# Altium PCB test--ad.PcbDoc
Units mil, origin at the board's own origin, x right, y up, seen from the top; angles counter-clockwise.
Board outline 2362.33 x 1685.17 mil, 2 copper layers (TopLayer, BottomLayer); 26 components, 98 nets, 129 pads, 106 vias.
Unrouted connection lines stored in the file: 5.
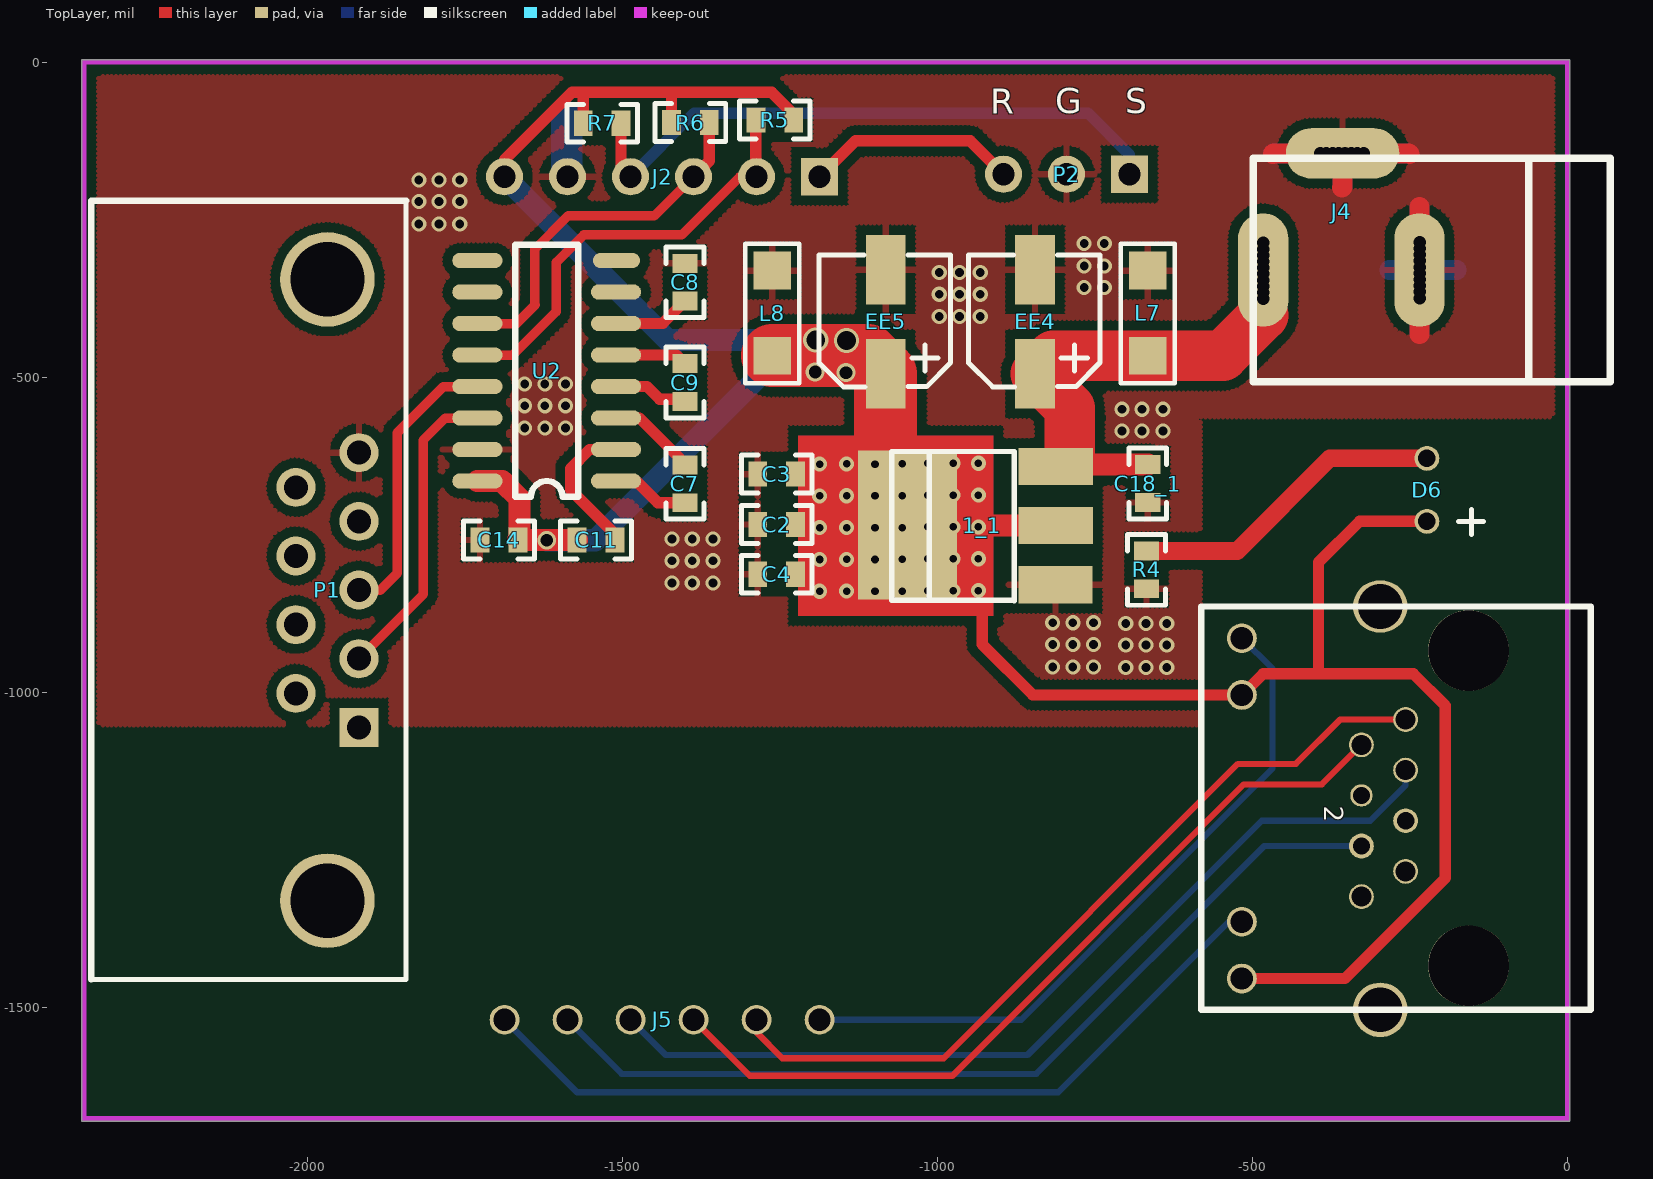
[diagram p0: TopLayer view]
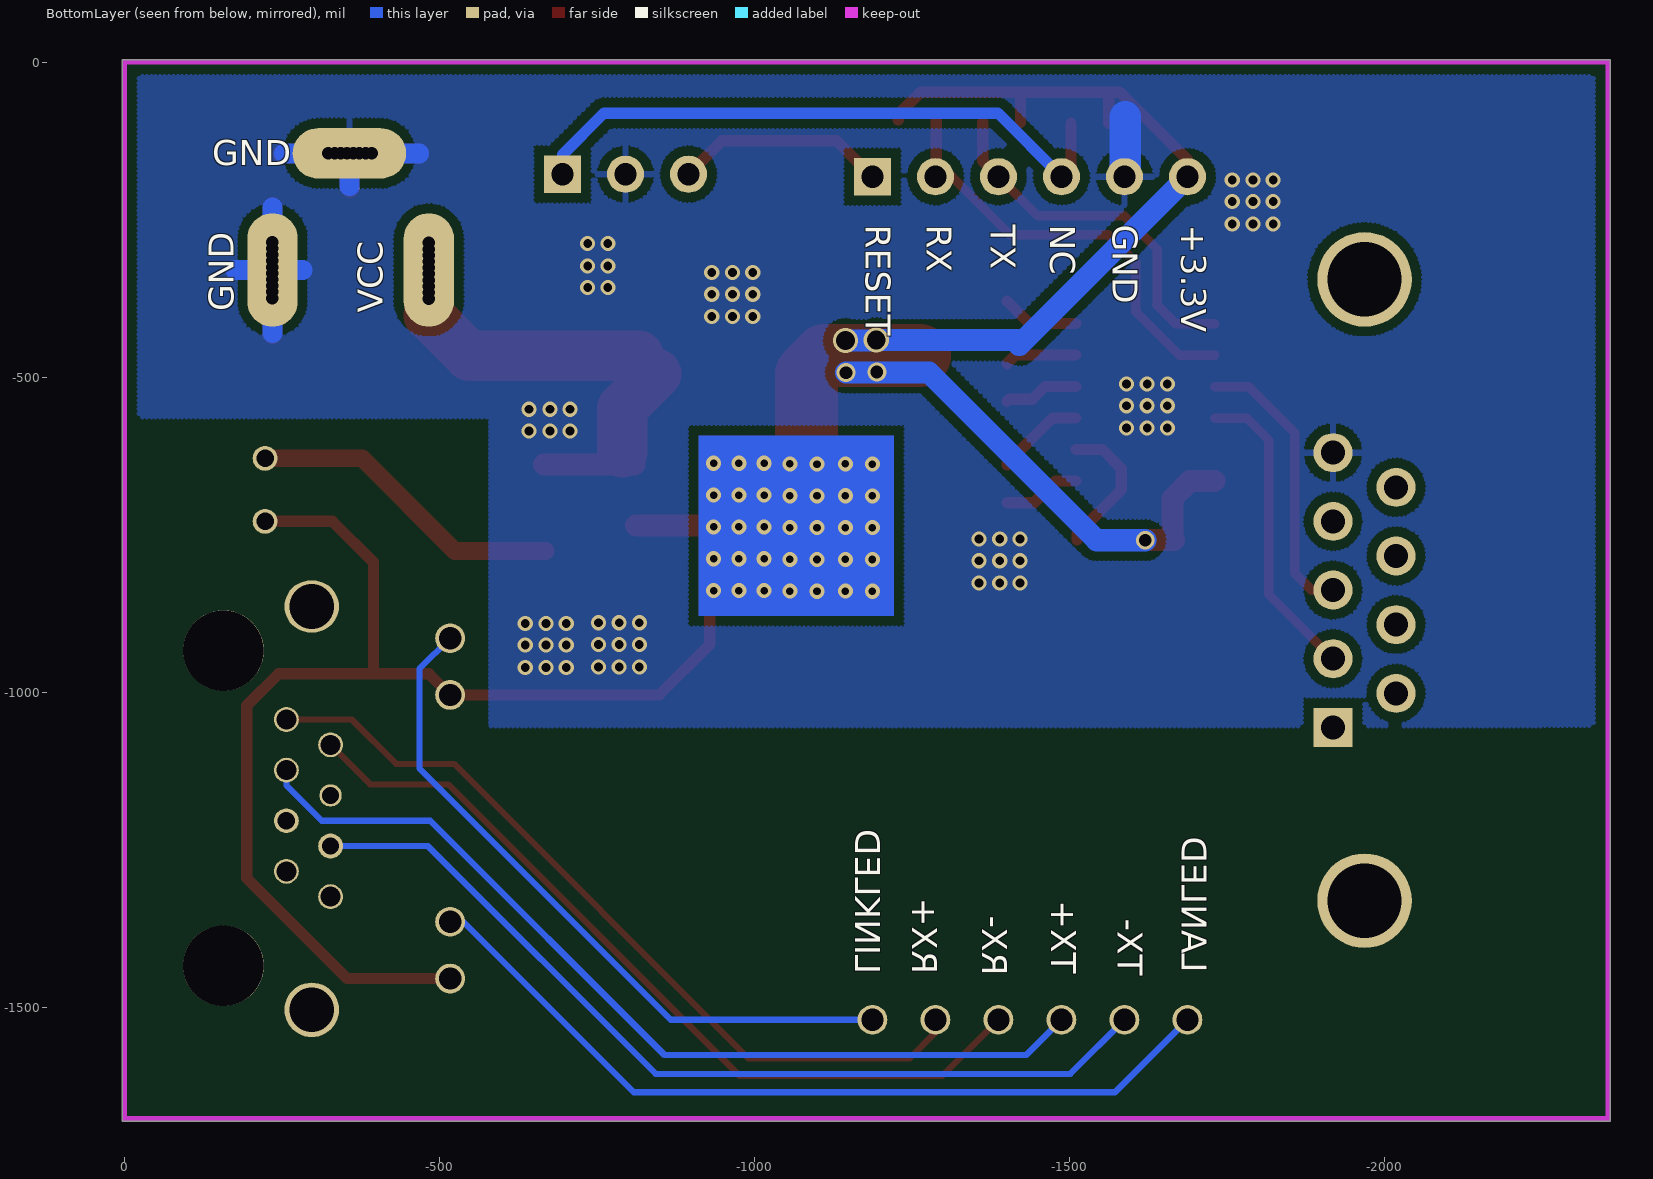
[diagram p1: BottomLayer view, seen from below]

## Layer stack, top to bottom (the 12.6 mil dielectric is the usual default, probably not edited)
TopLayer: signal copper 1.4
Dielectric: dielectric 12.6, FR-4, Dk 4.8
BottomLayer: signal copper 1.4

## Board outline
-2358.33,-1681.17 4,-1681.17 4,4 -2358.33,4

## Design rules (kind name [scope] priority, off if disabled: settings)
Clearance [All] p1: gap=15
FabricationTestPointUsage TestPointUsage [All] p1: valid=0 allowmultiple=FALSE
FabricationTestpoint Testpoint [All] p1: side=3 testpointundercomponent=TRUE minsize=40 maxsize=100 preferedsize=60 minholesize=20 maxholesize=40 preferedholesize=32 testpointgrid=1 allowsidetop=TRUE allowsidebottom=TRUE usegrid=TRUE gridtolerance=0.01
PolygonConnect [All] p1: connectstyle=Relief reliefconductorwidth=10 reliefentries=4 polygonreliefangle="90 Angle" airgapwidth=10
RoutingVias [All] p1: holewidth=28 width=50 viastyle="Through Hole" minholewidth=28 minwidth=50 maxholewidth=28 maxwidth=50
SilkscreenOverComponentPads [All] p1: minsilkscreentomaskgap=10
SolderMaskExpansion [All] p1: expansion=4
Width [All] p1: maxlimit=100 minlimit=6 preferedwidth=8
25 further rules are at their usual default settings.

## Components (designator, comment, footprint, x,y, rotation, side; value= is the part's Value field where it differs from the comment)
1_1 "LM1117-3.3V" 3-ASM-1117 -813,-828 r90 top
2 "Comment" PCBComponent_1 37,-864 r270 top
C2 "104" 2-R0603 -1285,-734 r0 top
C3 "104" 2-R0603 -1285,-654 r0 top
C4 "104" 2-R0603 -1285,-813 r0 top
C7 "0.1uf" 2-R0603 -1400.73,-699.43 r90 top
C8 "0.1uf" 2-R0603 -1400.45,-319.43 r270 top
C9 "0.1uf" 2-R0603 -1400.45,-478.62 r270 top
C11 "0.1uf" 2-R0603 -1571.73,-758.43 r0 top
C14 "0.1uf" 2-R0603 -1725.86,-758.43 r0 top
C18_1 "104" 2-R0603 -666,-699 r90 top
D6 "LED" ? -223,-729 r90 top
EE4 "100/10V" EC_D5.0_SMD -845,-495 r270 top
EE5 "100/10V" EC_D5.0_SMD -1082,-495 r270 top
J2 "Comment" HDR1X6#1 -1187,-182 r180 top
J4 "CON3" 3-POWER 73.32,-330.01 r90 top
J5 "Comment" HDR1X6#2 -1687,-1520 r0 top
L7 "9V稳压" 1206A -666,-466 r90 top
L8 "3.6V稳压" 1206A -1262,-466 r90 top
P1 "CONNECTOR DB9" "11-DB9RA/F ĸͷ" -1918,-1056 r90 top
P2 "Header 4H" HDR1X4H -695,-178 r180 top
R4 "1K" 2-R0603 -668,-836 r90 top
R5 "10K" 2-R0603 -1228,-92 r180 top
R6 "10K" 2-R0603 -1422,-96 r0 top
R7 "10K" 2-R0603 -1562,-97 r0 top
U2 "MAX3232CSE" 16-SO-16 -1510,-665 r90 top

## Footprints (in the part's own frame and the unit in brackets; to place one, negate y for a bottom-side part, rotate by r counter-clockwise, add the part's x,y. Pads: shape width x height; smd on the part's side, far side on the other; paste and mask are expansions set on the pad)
2-R0603 [mil]
  rect 30x40 smd: 1(0,0) 2(60,0)
  silkscreen extent -26,-30 86,30
3-ASM-1117 [mm]
  rect 1.5x3 smd: 1(-0.039,-0.013) 2(2.351,-0.023) 3(4.731,-0.023)
  rect 6x4 smd: 2(2.371,5.957)
  silkscreen extent -0.69,1.65 5.33,6.58
3-POWER [mil]
  oval 180x80 all layers, no hole: 1(0,556.18) 2(0,308.15)
  oval 80x180 all layers, no hole: 3(185.04,430.2)
  silkscreen extent -177,5 177,572
"11-DB9RA/F ĸͷ" [mil]
  rect 62x62 hole 38: 1(0,0)
  round 62 hole 38: 2(109,0) 3(218,0) 4(327,0) 5(436,0) 6(54,100) 7(163,100) 8(272,100) 9(381,100)
  round 150 hole 118.11: 10(-275,50) 11(711,50)
  silkscreen extent -400,-75 836,425
16-SO-16 [mil]
  oval 24x80 smd: 1(0,0) 2(50,0) 3(100,0) 4(150,0) 5(200,0) 6(250,0) 7(300,0) 9(350,220) 10(300,220) 11(250,220) 12(200,220) 13(150,220) 14(100,220) 15(50,220) 16(0,220)
  oval 24x75 smd: 8(350,-0.73)
  silkscreen extent -25,60 375,160
1206A [mil]
  rect 60x60 smd: 1(0,0) 2(135,0)
  silkscreen extent -44,-43 178,43
EC_D5.0_SMD [mm]
  rect 2.8x1.6 smd: 1(0,0) 2(-4.2,0)
  silkscreen extent -4.79,-2.68 0.52,2.62
HDR1X4H [mm]
  rect 1.5x1.5 hole 0.9: 1(0,0)
  round 1.5 hole 0.9: 2(2.54,0) 3(5.08,0)
HDR1X6#1 [mm]
  rect 1.5x1.5 hole 0.9: 1(0,0)
  round 1.5 hole 0.9: 2(2.54,0) 3(5.08,0) 4(7.62,0) 5(10.16,0) 6(12.7,0)
HDR1X6#2 [mm]
  round 1.2 hole 0.9: 1(0,0) 2(2.54,0) 3(5.08,0) 4(7.62,0) 5(10.16,0) 6(12.7,0)
PCBComponent_1 [mm]
  round 1 hole 0.8: 1(4.56,-7.464) 2(5.58,-9.244) 3(6.6,-7.464) 7(10.68,-7.464) 8(11.7,-9.244)
  round 0.9 hole 0.7: 4(7.62,-9.244)
  round 1 hole 0.7: 5(8.64,-7.464) 6(9.66,-9.244)
  round 1.2 hole 0.9: 9+(15,-14.064) 10-(12.71,-14.064) 11+(3.57,-14.064) 12-(1.28,-14.064)
  round 2.2 hole 1.8: A(16.265,-8.484)
  oval 2.1x2.2 hole 1.8: B(0,-8.484)
  round 3.25 hole 3.25: C(1.78,-4.924) D(14.485,-4.924)
  silkscreen extent 0,-15.7 16.26,0
? [mm]
  round 1 hole 0.7: 1(0,0) 2(2.54,0)
  silkscreen extent -0.53,-2.29 0.48,-1.27

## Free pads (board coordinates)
  round 19.68 hole 19.68: 3(-482.68,-375.6) 3(-234.68,-374.6) 4(-482.68,-365.75) 4(-234.68,-364.75) 5(-482.68,-355.91) 5(-323.43,-145.01) 5(-234.68,-354.91) 6(-482.68,-346.07) 6(-333.28,-145.01) 6(-234.68,-345.07) 7(-482.68,-336.23) 7(-343.12,-145.01) 7(-234.68,-335.23) 8(-482.68,-326.38) 8(-352.96,-145.01) 8(-234.68,-325.38) 9(-482.68,-316.54) 9(-362.8,-145.01) 9(-234.68,-315.54) 10(-482.68,-306.7) 10(-372.65,-145.01) 10(-234.68,-305.7) 11(-482.68,-296.86) 11(-382.49,-145.01) 11(-234.68,-295.86) 12(-482.68,-287.01) 12(-392.33,-145.01) 12(-234.68,-286.01)

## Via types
v1: diameter 24, hole 14, TopLayer to BottomLayer, tented both sides, 66 vias
v2: diameter 24, hole 12, TopLayer to BottomLayer, tented both sides, 35 vias
v3: diameter 30, hole 20, TopLayer to BottomLayer, 3 vias
v4: diameter 40, hole 30, TopLayer to BottomLayer, 2 vias

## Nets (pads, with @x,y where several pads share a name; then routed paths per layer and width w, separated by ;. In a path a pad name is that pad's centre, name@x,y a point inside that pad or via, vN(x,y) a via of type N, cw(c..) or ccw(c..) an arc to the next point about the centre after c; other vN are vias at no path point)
+5V: 
CMD: 
CSCL: 
CSDA: 
DM9000_RX+: 
DM9000_RX-: 
DM9000_TX+: 
DM9000_TX-: 
EMR: 
EMT: 
GND: 1_1.1 C2.1 C3.1 C4.1 C8.1 C14.1 C18_1.1 EE4.2 EE5.2 J2.5 J4.2 J4.3 L7.2 L8.2 P1.5 P2.2 pad.3@-234.68,-374.6 pad.4@-234.68,-364.75 pad.5@-234.68,-354.91 pad.5@-323.43,-145.01 pad.6@-234.68,-345.07 pad.6@-333.28,-145.01 pad.7@-234.68,-335.23 pad.7@-343.12,-145.01 pad.8@-234.68,-325.38 pad.8@-352.96,-145.01 pad.9@-234.68,-315.54 pad.9@-362.8,-145.01 pad.10@-234.68,-305.7 pad.10@-372.65,-145.01 pad.11@-234.68,-295.86 pad.11@-382.49,-145.01 pad.12@-234.68,-286.01 pad.12@-392.33,-145.01 R4.1 U2.15 | length 405.2
  TopLayer w31.5: -467.68,-146.01 -466.65,-144.97 J4.3@-427.68,-144.97 ; -357.68,-198.97 -356.88,-198.17 J4.3@-356.88,-176.01 ; J4.3@-286.68,-144.97 -251.72,-144.97 -250.68,-146.01 ; J4.2@-234.83,-405.01 -234.83,-431.86 -234.68,-432.01 ; J4.2@-234.83,-254.01 -234.83,-230.01
  BottomLayer w31.5: -467.72,-144.97 J4.3@-434.68,-144.97 ; -356.88,-197.21 J4.3@-356.88,-178.01 ; -282.68,-330.01 J4.2@-266.68,-330.01 ; J4.3@-278.68,-144.97 -252.88,-144.97 ; -234.83,-430.01 J4.2@-234.83,-410.01 ; J4.2@-234.83,-246.01 -234.83,-231.01 ; J4.2@-204.68,-330.01 -175.68,-330.01
  BottomLayer w50: -1588,-86.44 -1588,-122 -1588,-181 J2.5
  other v1: -701,-961 -669,-961 -636,-961 -817,-960 -785,-960 -752,-960 -701,-925.44 -669,-925.44 -636,-925.44 -817,-924.44 -785,-924.44 -752,-924.44 -701,-891 -669,-891 -636,-891 -817,-890 -785,-890 -752,-890 -1421,-827 -1389,-827 -1356,-827 -1421,-791.44 -1389,-791.44 -1356,-791.44 -1421,-757 -1389,-757 -1356,-757 -707,-585.44 -675,-585.44 -642,-585.44 -1655,-581 -1623,-581 -1590,-581 -707,-551 -675,-551 -642,-551 -1655,-545.44 -1623,-545.44 -1590,-545.44 -1655,-511 -1623,-511 -1590,-511 -997,-404 -965,-404 -932,-404 -997,-368.44 -965,-368.44 -932,-368.44 -767,-358 -735,-358 -997,-334 -965,-334 -932,-334 -767,-323.56 -735,-323.56 -767,-288 -735,-288 -1823,-257 -1791,-257 -1758,-257 -1823,-221.44 -1791,-221.44 -1758,-221.44 -1823,-187 -1791,-187 -1758,-187
GND_EATHER: 2.A 2.B
IRQ: 
LANLED: 2.12- J5.6 | length 1111
  BottomLayer w10: J5.6 -867,-1520 -468,-1121 -468,-963.1 2.12-
LDATA0: 
LDATA1: 
LDATA2: 
LDATA3: 
LDATA4: 
LDATA5: 
LDATA6: 
LDATA7: 
LDATA8: 
LDATA9: 
LDATA10: 
LDATA11: 
LDATA12: 
LDATA13: 
LDATA14: 
LDATA15: 
LINKLED: 2.10- J5.1 | length 1330
  BottomLayer w10: J5.1 -1572,-1635 -808,-1635 -537.41,-1364.41 2.10-
LNOE: 
LNWE: 
MCU-RX: J2.2 R5.2 U2.12 | length 696.3
  TopLayer w15: U2.12 -1674,-465 -1605,-396 -1605,-318 -1561,-274 -1405.42,-274 -1313.42,-182 J2.2
  TopLayer w18: R5.2 -1288,-181 J2.2
MCU-RX2: U2.9
MCU-RX-232: 
MCU-TX: J2.3 R6.2 U2.11 | length 588.8
  TopLayer w15: U2.11 -1668,-415 -1638,-385 -1639,-384 -1639,-297 -1586,-244 -1449,-244 J2.3
  TopLayer w18: J2.3 -1362,-157 R6.2
MCU-TX2: U2.10
MCULED: 
MCUREST: J2.1 P2.3 | length 337.6
  TopLayer w18: J2.1 -1130,-125 -948,-125 P2.3
NCS1: 
NET_AVDD25: 
NetC11_2: 
NetC12_2: 
NetC15_2: 
NetC16_2: 
NetC27_1: C7.1 U2.1 | length 123.5
  TopLayer w18: U2.1 -1478,-665 -1443.57,-699.43 C7.1
NetC27_2: C7.2 U2.3 | length 141.4
  TopLayer w18: U2.3 -1473,-565 -1400.73,-637.27 C7.2
NetC28_1: C9.1 U2.5 | length 115.2
  TopLayer w18: U2.5 -1414.07,-465 C9.1
NetC28_2: C9.2 U2.4 | length 119.3
  TopLayer w18: U2.4 -1461,-515 -1441,-535 -1404.07,-535 C9.2
NetC30_2: C11.2 U2.2 | length 227
  TopLayer w18: C11.2 -1511.73,-749.49 -1582,-679.22 -1582,-645 -1552,-615 U2.2
NetC31_2: C8.2 U2.6 | length 124.3
  TopLayer w18: U2.6 -1436.02,-415 C8.2
NetD1_2: D6.2 R4.2 | length 505.9
  TopLayer w28: R4.2 -524,-776 -377,-629 D6.2
NetD2_2: 
NetD3_2: 
NetR3_2: 
NetU2_2: 
NRESET: 
PA3: 
PA4: 
PA5: 
PA6: 
PC1: 
PC2: 
PC3: 
PC4: 
PC5: 
PC6: 
PC7: 
PC-RX: P1.2 U2.14 | length 489.7
  TopLayer w15: P1.2 -1816,-845 -1816,-600 -1781,-565 U2.14
PC-RX2: P1.8 U2.8
PC-TX: P1.3 U2.13 | length 452.4
  TopLayer w15: P1.3 -1884,-838 -1857,-811 -1857,-588 -1784,-515 U2.13
PC-TX2: P1.7 U2.7
PD7: 
PE1: 
PE2: 
PE3: 
PE5: 
PE6: 
PG0: 
PG1: 
RX+: 2.1 J5.5 | length 1289.8
  TopLayer w10: J5.5 -1287,-1540 -1246,-1581 -990,-1581 -523,-1114 -431,-1114 -360.53,-1043.53 2.1
RX-: 2.2 J5.4 | length 1314.5
  TopLayer w10: J5.4 -1298,-1609 -976,-1609 -513.5,-1146.5 -389.74,-1146.5 2.2
SPICLK: 
SPICS: 
SPIMISO: 
SPIMOSI: 
SWIM: J2.4 P2.1 R7.2 | length 983.4
  TopLayer w18: R7.2 -1502,-167 J2.4
  BottomLayer w18: J2.4 -1386,-81 -761,-81 -695,-147 P2.1
TX+: 2.3 J5.3 | length 1454.7
  BottomLayer w10: J5.3 -1431,-1576 -857,-1576 -485,-1204 -313,-1204 -256.84,-1147.84 2.3
TX-: 2.6 J5.2 | length 1445.5
  BottomLayer w10: J5.2 -1501,-1606 -843,-1606 -481.32,-1244.32 2.6
VBAT: 
VCC-5: 1_1.3 C18_1.2 EE4.1 J4.1 L7.1 P1.9 pad.3@-482.68,-375.6 pad.4@-482.68,-365.75 pad.5@-482.68,-355.91 pad.6@-482.68,-346.07 pad.7@-482.68,-336.23 pad.8@-482.68,-326.38 pad.9@-482.68,-316.54 pad.10@-482.68,-306.7 pad.11@-482.68,-296.86 pad.12@-482.68,-287.01 | length 650.1
  TopLayer w35: 1_1.3@-809.35,-639 C18_1.2
  TopLayer w80: EE4.1@-844,-495 -790,-549 1_1.3@-790,-619.65 ; EE4.1@-816,-466 L7.1 -547,-466 J4.1@-482.87,-401.87
VCPA: 
VDD33V: 1_1.2 2.9+ 2.11+ C2.2 C3.2 C4.2 C11.1 C14.2 D6.1 EE5.1 J2.6 L8.1 P1.4 R5.1 R6.1 R7.1 U2.16 | length 4697.8
  TopLayer w18: J2.6@-1687,-155 -1580,-48 -1556,-48 ; R7.1 -1562,-54 -1556,-48 ; R6.1 -1422,-54 -1416,-48 ; R5.1 -1228,-83.06 -1263.06,-48 -1416,-48 ; -927,-868 -929,-870 -929,-924 -848.43,-1004.57 2.11+ -483.12,-971 -395,-971 ; 2.9+ -353.24,-1454.57 -193.67,-1295 -193.67,-1021.67 -244.34,-971 -395,-971 ; D6.1 -330,-729 -395,-794 -395,-971 ; -1556,-48 -1416,-48
  TopLayer w35: U2.16 -1691,-665 -1663,-693 -1663,-755.57 C14.2 C11.1 ; 1_1.2@-1047.52,-734.65 -1046.73,-735.43 1_1.2@-812.09,-735.43
  TopLayer w80: -1082,-598 -1082,-700.17 1_1.2@-1047.52,-734.65
  TopLayer w100: L8.1 -1111,-466 EE5.1 -1082,-598
  BottomLayer w35: J2.6 -1428,-441 ; v3(-1620,-759) -1543,-759 -1277,-493 v3(-1145,-493) ; -1420,-449 -1428,-441 ; v4(-1193,-441) v4@-1195,-441 ; v4(-1144,-442) -1194,-442 v4@-1195,-441 ; -1428,-441 v4@-1195,-441
  other v2: -1187,-840 -1144,-839.8 -1099,-840 -1056,-839.8 -1015,-838.8 -975,-838.8 -935,-838.8 -1187,-789.5 -1144,-789.3 -1099,-789.5 -1056,-789.3 -1015,-788.3 -975,-788.3 -935,-788.3 -1187,-739 -1144,-738.8 -1099,-739 -1056,-738.8 -1015,-737.8 -975,-737.8 -935,-737.8 -1187,-688.5 -1144,-688.3 -1099,-688.5 -1056,-688.3 -1015,-687.3 -975,-687.3 -935,-687.3 -1187,-638 -1144,-637.8 -1099,-638 -1056,-637.8 -1015,-636.8 -975,-636.8 -935,-636.8
  other v3: -1194,-492
X1: 
X2: 
XTI: 
XTO: 
pads on no net: 2.4 2.5 2.7 2.8 2.C 2.D P1.1 P1.6 P1.10 P1.11

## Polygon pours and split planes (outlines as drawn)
GND on TopLayer "TopLayer-GND" (hatched 90Degree grid 7 track 8, remove dead copper, pour order 2): -2354.33,0 -2354.33,-1052 -582,-1052 -582,-1039 -582,-567 -583,-566 -583,-565 -583,-562 -582,-563 -570,-563 0,-563 1,-562 1,0 -2355,0
GND on BottomLayer "BottomLayer-GND" (hatched 90Degree grid 7 track 8, remove dead copper, pour order 4): -2353,0 -2354.33,-1.33 -2354.33,-1053 -2254,-1053 -2253,-1054 -581,-1054 -581,-1039 -581,-1027 -581,-564 -580,-563 -1,-563 0,-562 0,0 -2354.33,0

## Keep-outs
KeepOutLayer:
  lines w8: -2354.33,-1677.17 -2354.33,0 0,0 0,-1677.17 -2354.33,-1677.17

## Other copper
TopLayer:
  rectangle net VDD33V: -1221,-879 -911,-593
BottomLayer:
  rectangle net VDD33V: -1221,-879 -911,-593

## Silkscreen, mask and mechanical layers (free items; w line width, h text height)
TopOverlay:
  lines w8: -75.74,-153.86 -32.43,-153.86
  text "G" at -813,-81 h40
  text "S" at -702,-81 h40
  text "R" at -916,-82 h40
BottomOverlay:
  text "GND" at -138.93,-163.83 h40
  text "+3.3V" at -1677,-257.98 h40 r90
  text "GND" at -1568,-257.98 h40 r90
  text "NC" at -1469,-257.98 h40 r90
  text "TX" at -1375,-257.98 h40 r90
  text "RX" at -1273,-257.98 h40 r90
  text "RESET" at -1176,-257.98 h40 r90
  text "GND" at -172.93,-395.83 h40 r270
  text "VCC" at -409.93,-397.83 h40 r270
  text "LANLED" at -1678,-1445.02 h40 r90
  text "TX+" at -1471,-1447.02 h40 r90
  text "RX+" at -1250,-1448.02 h40 r90
  text "LINKLED" at -1160,-1448.02 h40 r90
  text "TX-" at -1576,-1450.02 h40 r90
  text "RX-" at -1361,-1450.02 h40 r90
BottomSolder:
  rectangle: -1221,-879 -911,-593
